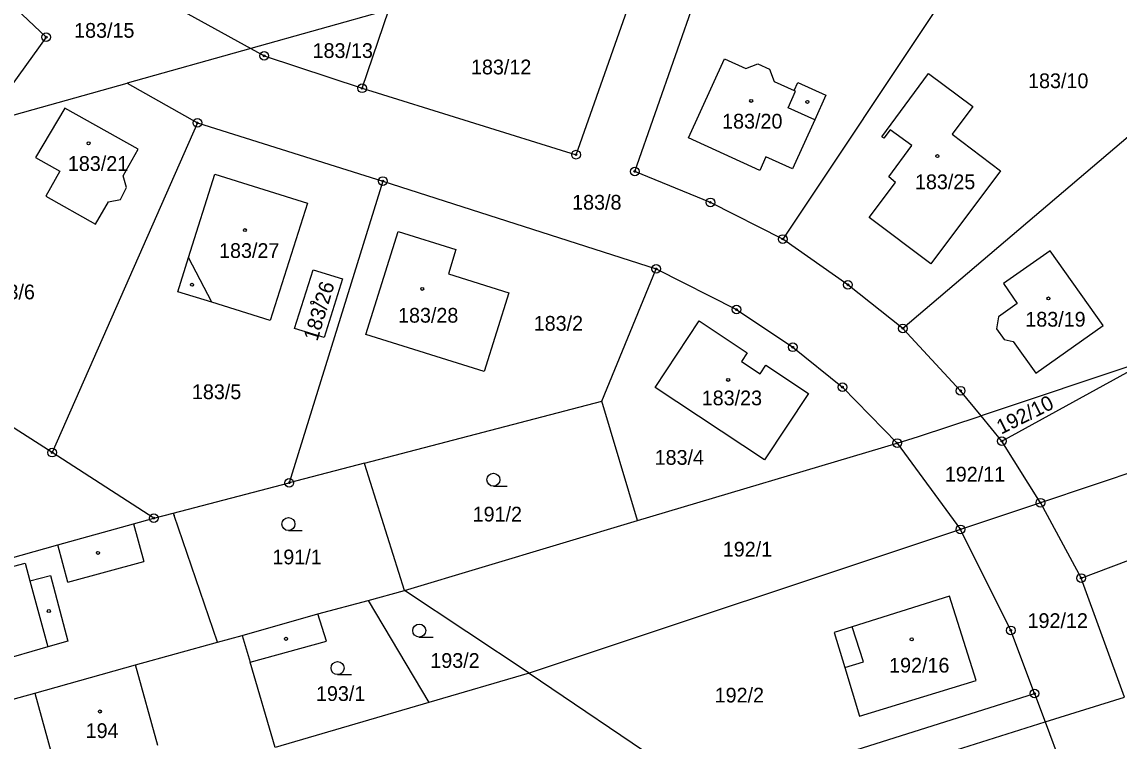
# Model space of a CAD drawing. Extents: x -762263 to -760336, y -1154405 to -1152076.
# Drawn here: x -761336.3 to -761209.8, y -1152546.3 to -1152463.4 of the extents above; entities that cross this region are included whole.
import ezdxf

# ---------------------------------------------------------------- set-up
doc = ezdxf.new("R2010")
doc.units = 0
for name, color, linetype in [('Vrstva 1', 7, 'Continuous'), ('Vrstva 18', 7, 'Continuous'), ('Vrstva 19', 7, 'Continuous'), ('Vrstva 24', 7, 'Continuous'), ('Vrstva 25', 7, 'Continuous'), ('Vrstva 4', 7, 'Continuous')]:
    doc.layers.add(name, color=color, linetype=linetype)

msp = doc.modelspace()

# ---------------------------------------------------------------- linework, layer by layer
at = {"layer": 'Vrstva 1'}
for p, q in [((-761265.65, -1152480.62), (-761255.32, -1152451.13)), ((-761223.61, -1152450.9), (-761248.59, -1152488.42)), ((-761272.42, -1152478.69), (-761263.54, -1152453.43)), ((-761343.27, -1152455.9), (-761333.49, -1152465.14)), ((-761327.79, -1152456.59), (-761309.91, -1152466.44)), ((-761293.98, -1152461.97), (-761309.91, -1152466.44)), ((-761297.08, -1152471.04), (-761293.98, -1152461.97)), ((-761333.49, -1152465.14), (-761340.65, -1152475.06)), ((-761194.96, -1152464.84), (-761234.74, -1152498.72)), ((-761309.91, -1152466.44), (-761324.16, -1152470.44)), ((-761309.91, -1152466.44), (-761308.37, -1152467.29)), ((-761308.37, -1152467.29), (-761297.08, -1152471.04)), ((-761259.45, -1152476.75), (-761255.31, -1152467.63)), ((-761255.31, -1152467.63), (-761252.86, -1152468.74)), ((-761252.86, -1152468.74), (-761251.47, -1152468.21)), ((-761251.47, -1152468.21), (-761250.1, -1152468.85)), ((-761250.1, -1152468.85), (-761249.56, -1152470.25)), ((-761237.17, -1152476.62), (-761231.77, -1152469.33)), ((-761231.77, -1152469.33), (-761226.67, -1152473.15)), ((-761340.65, -1152475.06), (-761324.16, -1152470.44)), ((-761324.16, -1152470.44), (-761316.07, -1152475.03)), ((-761297.08, -1152471.04), (-761272.42, -1152478.69)), ((-761249.56, -1152470.25), (-761247.28, -1152471.29)), ((-761247.28, -1152471.29), (-761246.85, -1152470.35)), ((-761246.85, -1152470.35), (-761243.61, -1152471.84)), ((-761243.61, -1152471.84), (-761244.89, -1152474.67)), ((-761331.35, -1152473.31), (-761334.73, -1152479.03)), ((-761322.91, -1152478.04), (-761331.35, -1152473.31)), ((-761226.67, -1152473.15), (-761229.07, -1152476.34)), ((-761316.07, -1152475.03), (-761332.81, -1152513.05)), ((-761316.07, -1152475.03), (-761294.69, -1152481.73)), ((-761244.89, -1152474.67), (-761247.46, -1152480.34)), ((-761236.2, -1152475.82), (-761236.93, -1152476.8)), ((-761233.71, -1152477.65), (-761236.2, -1152475.82)), ((-761229.07, -1152476.34), (-761223.48, -1152480.54)), ((-761251.23, -1152480.5), (-761259.45, -1152476.75)), ((-761236.93, -1152476.8), (-761237.17, -1152476.62)), ((-761236.37, -1152481.26), (-761233.71, -1152477.65)), ((-761334.73, -1152479.03), (-761331.92, -1152480.6)), ((-761324.62, -1152481.14), (-761322.91, -1152478.04)), ((-761250.52, -1152478.95), (-761251.23, -1152480.5)), ((-761247.46, -1152480.34), (-761250.52, -1152478.95)), ((-761331.92, -1152480.6), (-761333.53, -1152483.49)), ((-761324.25, -1152482.49), (-761324.62, -1152481.14)), ((-761317.09, -1152490.55), (-761314.06, -1152480.93)), ((-761314.06, -1152480.93), (-761303.39, -1152484.29)), ((-761256.93, -1152484.19), (-761265.65, -1152480.62)), ((-761235.58, -1152481.89), (-761236.37, -1152481.26)), ((-761223.48, -1152480.54), (-761231.52, -1152491.27)), ((-761324.94, -1152483.85), (-761324.25, -1152482.49)), ((-761294.69, -1152481.73), (-761305.47, -1152516.52)), ((-761294.69, -1152481.73), (-761263.17, -1152491.86)), ((-761238.61, -1152485.94), (-761235.58, -1152481.89)), ((-761333.53, -1152483.49), (-761327.82, -1152486.71)), ((-761327.82, -1152486.71), (-761326.32, -1152484.13)), ((-761326.32, -1152484.13), (-761324.94, -1152483.85)), ((-761303.39, -1152484.29), (-761307.66, -1152497.81)), ((-761248.59, -1152488.42), (-761256.93, -1152484.19)), ((-761231.52, -1152491.27), (-761238.61, -1152485.94)), ((-761296.63, -1152499.42), (-761292.92, -1152487.54)), ((-761292.92, -1152487.54), (-761286.28, -1152489.63)), ((-761241.07, -1152493.7), (-761248.59, -1152488.42)), ((-761286.28, -1152489.63), (-761287.12, -1152492.45)), ((-761217.77, -1152489.77), (-761223.14, -1152493.56)), ((-761211.65, -1152498.4), (-761217.77, -1152489.77)), ((-761318.33, -1152494.49), (-761317.09, -1152490.55)), ((-761304.87, -1152498.73), (-761302.72, -1152491.97)), ((-761302.72, -1152491.97), (-761299.33, -1152493.02)), ((-761287.12, -1152492.45), (-761280.16, -1152494.61)), ((-761269.46, -1152507.1), (-761263.17, -1152491.86)), ((-761263.17, -1152491.86), (-761253.92, -1152496.55)), ((-761299.33, -1152493.02), (-761301.44, -1152499.76)), ((-761234.74, -1152498.72), (-761241.07, -1152493.7)), ((-761223.14, -1152493.56), (-761221.55, -1152495.87)), ((-761314.4, -1152495.71), (-761318.33, -1152494.49)), ((-761280.16, -1152494.61), (-761283, -1152503.69)), ((-761307.66, -1152497.81), (-761314.4, -1152495.71)), ((-761253.92, -1152496.55), (-761247.43, -1152500.9)), ((-761221.55, -1152495.87), (-761223.73, -1152497.39)), ((-761263.28, -1152505.52), (-761258.24, -1152497.84)), ((-761258.24, -1152497.84), (-761252.69, -1152501.53)), ((-761223.73, -1152497.39), (-761223.95, -1152498.78)), ((-761301.44, -1152499.76), (-761304.87, -1152498.73)), ((-761228.08, -1152505.91), (-761234.74, -1152498.72)), ((-761223.95, -1152498.78), (-761223.08, -1152500)), ((-761219.4, -1152503.89), (-761211.65, -1152498.4)), ((-761283, -1152503.69), (-761296.63, -1152499.42)), ((-761223.08, -1152500), (-761222.01, -1152500.22)), ((-761222.01, -1152500.22), (-761219.4, -1152503.89)), ((-761252.69, -1152501.53), (-761253.36, -1152502.53)), ((-761247.43, -1152500.9), (-761241.71, -1152505.5)), ((-761253.36, -1152502.53), (-761251.2, -1152503.97)), ((-761251.2, -1152503.97), (-761250.53, -1152502.97)), ((-761250.53, -1152502.97), (-761245.63, -1152506.24)), ((-761206.07, -1152502.23), (-761225.73, -1152508.79)), ((-761223.33, -1152511.72), (-761206.07, -1152502.23)), ((-761332.81, -1152513.05), (-761344.37, -1152505.6)), ((-761250.69, -1152513.87), (-761263.28, -1152505.52)), ((-761241.71, -1152505.5), (-761235.4, -1152511.94)), ((-761245.63, -1152506.24), (-761250.69, -1152513.87)), ((-761225.73, -1152508.79), (-761228.08, -1152505.91)), ((-761180.06, -1152505.88), (-761218.89, -1152518.82)), ((-761296.81, -1152514.25), (-761269.46, -1152507.1)), ((-761265.32, -1152520.89), (-761269.46, -1152507.1)), ((-761232.94, -1152511.2), (-761225.73, -1152508.79)), ((-761223.33, -1152511.72), (-761225.73, -1152508.79)), ((-761265.32, -1152520.89), (-761235.4, -1152511.94)), ((-761235.4, -1152511.94), (-761232.94, -1152511.2)), ((-761235.4, -1152511.94), (-761228.11, -1152521.9)), ((-761218.89, -1152518.82), (-761223.33, -1152511.72)), ((-761321.1, -1152520.6), (-761332.81, -1152513.05)), ((-761296.81, -1152514.25), (-761305.47, -1152516.52)), ((-761296.76, -1152514.41), (-761296.81, -1152514.25)), ((-761292.21, -1152528.95), (-761296.76, -1152514.41)), ((-761214.19, -1152527.51), (-761177.23, -1152513.66)), ((-761318.84, -1152520.01), (-761305.47, -1152516.52)), ((-761218.89, -1152518.82), (-761228.11, -1152521.9)), ((-761218.89, -1152518.82), (-761214.19, -1152527.51)), ((-761323.44, -1152521.25), (-761321.1, -1152520.6)), ((-761321.1, -1152520.6), (-761318.84, -1152520.01)), ((-761318.84, -1152520.01), (-761318.74, -1152520.3)), ((-761313.74, -1152534.91), (-761318.74, -1152520.3)), ((-761332.16, -1152523.69), (-761323.44, -1152521.25)), ((-761292.21, -1152528.95), (-761265.32, -1152520.89)), ((-761228.11, -1152521.9), (-761277.83, -1152538.47)), ((-761222.3, -1152533.54), (-761228.11, -1152521.9)), ((-761350.22, -1152528.73), (-761332.16, -1152523.69)), ((-761209.19, -1152541.23), (-761214.19, -1152527.51)), ((-761296.38, -1152530.1), (-761292.21, -1152528.95)), ((-761277.83, -1152538.47), (-761292.21, -1152528.95)), ((-761229.35, -1152529.6), (-761240.59, -1152533.12)), ((-761226.3, -1152539.31), (-761229.35, -1152529.6)), ((-761302.19, -1152531.65), (-761296.38, -1152530.1)), ((-761296.38, -1152530.1), (-761289.4, -1152541.86)), ((-761310.89, -1152534.12), (-761302.19, -1152531.65)), ((-761240.59, -1152533.12), (-761242.67, -1152533.77)), ((-761313.74, -1152534.91), (-761310.89, -1152534.12)), ((-761310.89, -1152534.12), (-761309.97, -1152537.2)), ((-761242.67, -1152533.77), (-761241.43, -1152537.84)), ((-761219.56, -1152540.83), (-761222.3, -1152533.54)), ((-761323.19, -1152537.52), (-761313.74, -1152534.91)), ((-761307.11, -1152547.04), (-761309.97, -1152537.2)), ((-761334.8, -1152540.8), (-761323.19, -1152537.52)), ((-761277.83, -1152538.47), (-761289.4, -1152541.86)), ((-761277.83, -1152538.47), (-761261.81, -1152549.3)), ((-761241.43, -1152537.84), (-761239.73, -1152543.43)), ((-761239.73, -1152543.43), (-761226.3, -1152539.31)), ((-761342.71, -1152542.92), (-761334.8, -1152540.8)), ((-761256.99, -1152552.61), (-761219.56, -1152540.83)), ((-761219.56, -1152540.83), (-761218.33, -1152544.1)), ((-761289.4, -1152541.86), (-761307.11, -1152547.04)), ((-761218.33, -1152544.1), (-761209.19, -1152541.23)), ((-761253.35, -1152555.1), (-761218.33, -1152544.1)), ((-761218.33, -1152544.1), (-761215.48, -1152551.69))]:
    msp.add_line(p, q, dxfattribs=at)
at = {"layer": 'Vrstva 24'}
for centre, radius in [((-761333.49, -1152465.14), 0.5), ((-761333.49, -1152465.14), 0.1), ((-761308.37, -1152467.29), 0.5), ((-761308.37, -1152467.29), 0.1), ((-761297.08, -1152471.04), 0.5), ((-761297.08, -1152471.04), 0.1), ((-761316.07, -1152475.03), 0.5), ((-761316.07, -1152475.03), 0.1), ((-761272.42, -1152478.69), 0.5), ((-761272.42, -1152478.69), 0.1), ((-761265.65, -1152480.62), 0.5), ((-761294.69, -1152481.73), 0.5), ((-761265.65, -1152480.62), 0.1), ((-761294.69, -1152481.73), 0.1), ((-761256.93, -1152484.19), 0.5), ((-761256.93, -1152484.19), 0.1), ((-761248.59, -1152488.42), 0.5), ((-761248.59, -1152488.42), 0.1), ((-761263.17, -1152491.86), 0.5), ((-761263.17, -1152491.86), 0.1), ((-761241.07, -1152493.7), 0.5), ((-761241.07, -1152493.7), 0.1), ((-761253.92, -1152496.55), 0.5), ((-761253.92, -1152496.55), 0.1), ((-761234.74, -1152498.72), 0.5), ((-761234.74, -1152498.72), 0.1), ((-761247.43, -1152500.9), 0.5), ((-761247.43, -1152500.9), 0.1), ((-761241.71, -1152505.5), 0.5), ((-761241.71, -1152505.5), 0.1), ((-761228.08, -1152505.91), 0.5), ((-761228.08, -1152505.91), 0.1), ((-761235.4, -1152511.94), 0.5), ((-761235.4, -1152511.94), 0.1), ((-761223.33, -1152511.72), 0.5), ((-761223.33, -1152511.72), 0.1), ((-761332.81, -1152513.05), 0.5), ((-761332.81, -1152513.05), 0.1), ((-761305.47, -1152516.52), 0.5), ((-761305.47, -1152516.52), 0.1), ((-761218.89, -1152518.82), 0.5), ((-761218.89, -1152518.82), 0.1), ((-761321.1, -1152520.6), 0.5), ((-761321.1, -1152520.6), 0.1), ((-761228.11, -1152521.9), 0.5), ((-761228.11, -1152521.9), 0.1), ((-761214.19, -1152527.51), 0.5), ((-761214.19, -1152527.51), 0.1), ((-761222.3, -1152533.54), 0.5), ((-761222.3, -1152533.54), 0.1), ((-761219.56, -1152540.83), 0.5), ((-761219.56, -1152540.83), 0.1)]:
    msp.add_circle(centre, radius, dxfattribs=at)
at = {"layer": 'Vrstva 25'}
for p, q in [((-761281.95, -1152516.92), (-761280.35, -1152516.92)), ((-761305.57, -1152522.03), (-761303.97, -1152522.03)), ((-761290.49, -1152534.32), (-761288.89, -1152534.32)), ((-761299.91, -1152538.64), (-761298.31, -1152538.64))]:
    msp.add_line(p, q, dxfattribs=at)
for centre, radius in [((-761252.23, -1152472.49), 0.175), ((-761245.75, -1152472.6), 0.175), ((-761328.61, -1152477.38), 0.175), ((-761230.76, -1152478.86), 0.175), ((-761310.59, -1152487.39), 0.175), ((-761316.68, -1152493.69), 0.175), ((-761290.15, -1152494.17), 0.175), ((-761217.96, -1152495.27), 0.175), ((-761302.83, -1152495.75), 0.175), ((-761254.88, -1152504.66), 0.175), ((-761281.95, -1152516.17), 0.75), ((-761305.57, -1152521.28), 0.75), ((-761327.53, -1152524.61), 0.175), ((-761333.19, -1152531.31), 0.175), ((-761290.49, -1152533.57), 0.75), ((-761305.86, -1152534.52), 0.175), ((-761233.72, -1152534.58), 0.175), ((-761299.91, -1152537.89), 0.75), ((-761327.31, -1152542.9), 0.175)]:
    msp.add_circle(centre, radius, dxfattribs=at)
at = {"layer": 'Vrstva 4'}
for p, q in [((-761247.96, -1152473.28), (-761247.1, -1152471.37)), ((-761247.1, -1152471.37), (-761247.28, -1152471.29)), ((-761244.89, -1152474.67), (-761247.96, -1152473.28)), ((-761314.4, -1152495.71), (-761317.09, -1152490.55)), ((-761323.44, -1152521.25), (-761322.24, -1152525.59)), ((-761330.99, -1152527.99), (-761332.16, -1152523.69)), ((-761345.2, -1152528.21), (-761335.91, -1152525.78)), ((-761335.91, -1152525.78), (-761335.38, -1152527.84)), ((-761330.99, -1152527.99), (-761322.24, -1152525.59)), ((-761335.38, -1152527.84), (-761333.01, -1152527.22)), ((-761335.38, -1152527.84), (-761333.31, -1152535.45)), ((-761333.01, -1152527.22), (-761331.02, -1152534.8)), ((-761301.17, -1152534.8), (-761302.19, -1152531.65)), ((-761239.27, -1152537.18), (-761240.59, -1152533.12)), ((-761333.31, -1152535.45), (-761342.38, -1152538.07)), ((-761331.02, -1152534.8), (-761333.31, -1152535.45)), ((-761309.97, -1152537.2), (-761301.17, -1152534.8)), ((-761241.43, -1152537.84), (-761239.27, -1152537.18)), ((-761320.61, -1152546.81), (-761323.19, -1152537.52)), ((-761334.8, -1152540.8), (-761331.82, -1152551.54))]:
    msp.add_line(p, q, dxfattribs=at)

# ---------------------------------------------------------------- texts
at = {"layer": 'Vrstva 18'}
for s, p in [('183/15', (-761330.277, -1152465.21)), ('183/13', (-761302.787, -1152467.54)), ('183/12', (-761284.527, -1152469.43)), ('183/10', (-761220.307, -1152471.02)), ('183/8', (-761272.867, -1152485.03)), ('183/6', (-761340.487, -1152495.37)), ('183/2', (-761277.297, -1152498.99)), ('183/5', (-761316.697, -1152506.88)), ('183/4', (-761263.357, -1152514.45)), ('192/11', (-761229.902, -1152516.38)), ('191/2', (-761284.337, -1152520.99)), ('192/1', (-761255.497, -1152525.03)), ('191/1', (-761307.427, -1152525.93)), ('192/12', (-761220.367, -1152533.27)), ('193/2', (-761289.217, -1152537.87)), ('193/1', (-761302.397, -1152541.68)), ('192/2', (-761256.437, -1152541.86))]:
    msp.add_text(s, height=1.7, dxfattribs=at).set_placement(p)
msp.add_text('192/10', height=1.7, rotation=26.58524, dxfattribs=at).set_placement((-761223.404, -1152510.988))
at = {"layer": 'Vrstva 19'}
for s, p in [('183/20', (-761255.577, -1152475.68)), ('183/21', (-761330.997, -1152480.56)), ('183/25', (-761233.347, -1152482.67)), ('183/27', (-761313.567, -1152490.6)), ('183/28', (-761292.937, -1152498.06)), ('183/19', (-761220.627, -1152498.52)), ('183/23', (-761257.927, -1152507.59)), ('192/16', (-761236.327, -1152538.41)), ('194', (-761328.947, -1152545.96))]:
    msp.add_text(s, height=1.7, dxfattribs=at).set_placement(p)
msp.add_text('183/26', height=1.7, rotation=73.16671, dxfattribs=at).set_placement((-761302.247, -1152500.282))

doc.saveas('drawing.dxf')
